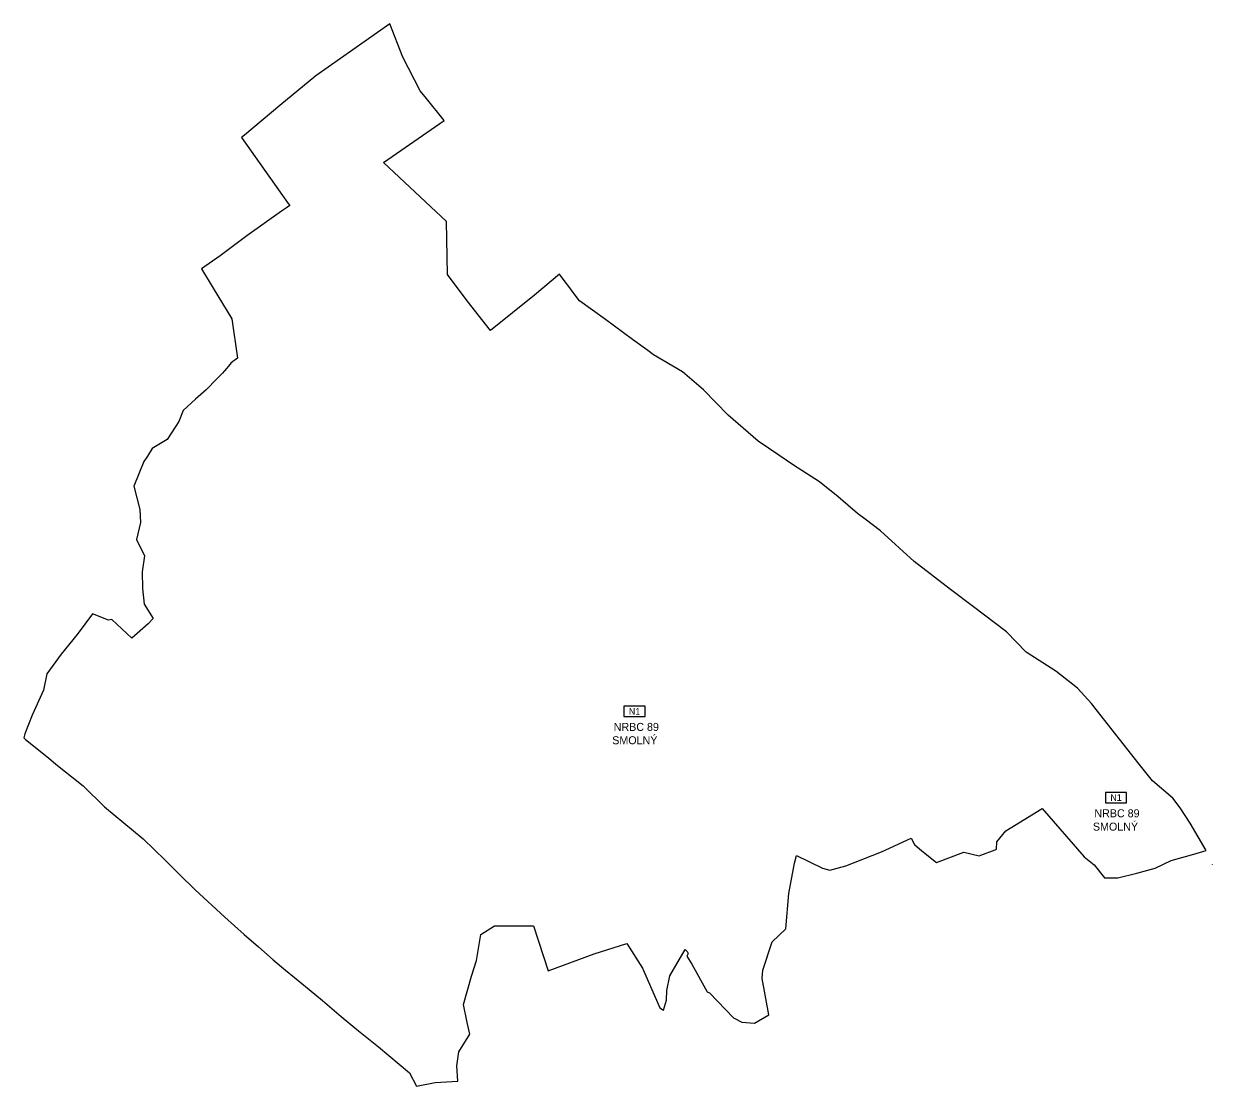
# Model space of a CAD drawing. Extents: x -546680 to -530218, y -1046521 to -1035695.
# Drawn here: x -543673 to -541891, y -1037288 to -1035695 of the extents above; entities that cross this region are included whole.
import ezdxf

# ---------------------------------------------------------------- set-up
doc = ezdxf.new("R2010")
doc.units = 0
for name, color, linetype in [('Vrstva 18', 7, 'Continuous'), ('Vrstva 3', 7, 'Continuous'), ('Vrstva 30', 7, 'Continuous'), ('Vrstva 82', 7, 'Continuous')]:
    doc.layers.add(name, color=color, linetype=linetype)

msp = doc.modelspace()

# ---------------------------------------------------------------- linework, layer by layer
at = {"layer": 'Vrstva 18'}
msp.add_line((-541891, -1036954.4), (-541890.8, -1036954.9), dxfattribs=at)
for points in [[(-541899.8, -1036934.3), (-541923.9, -1036893.3), (-541939.1, -1036869.9), (-541949.7, -1036855.6), (-541980.5, -1036829.7), (-542000.3, -1036804.7), (-542065.1, -1036722.5), (-542069.8, -1036716.4), (-542072.1, -1036713.8), (-542092.8, -1036690.7), (-542125.6, -1036665.3), (-542169.9, -1036636.7), (-542199.3, -1036606), (-542248.8, -1036568.9), (-542283.5, -1036542.7), (-542337.9, -1036500.9), (-542388.3, -1036455), (-542411.4, -1036437.3), (-542422.8, -1036428.7), (-542452, -1036403.6), (-542480, -1036381.3), (-542519, -1036356.5), (-542540.9, -1036341.6), (-542571.9, -1036320.4), (-542617, -1036281.3), (-542653.7, -1036243.4), (-542685.1, -1036216.3), (-542728.5, -1036190.8), (-542737.3, -1036184.4), (-542760.1, -1036167.7), (-542800.8, -1036138), (-542839.6, -1036109.9), (-542850.5, -1036095.4), (-542852.5, -1036092.7), (-542864, -1036077.3), (-542869.7, -1036069.8), (-542907.1, -1036101.7), (-542973.1, -1036154.5), (-543008.4, -1036110.2), (-543037.8, -1036070.6), (-543039.3, -1035990.9), (-543133.7, -1035902.3), (-543042.6, -1035839.4), (-543069.2, -1035806.4), (-543078.5, -1035794.9), (-543104.7, -1035744.6), (-543124.3, -1035694.5), (-543234.9, -1035772.4), (-543289.2, -1035817), (-543341.9, -1035861.5), (-543346.5, -1035865.2), (-543276.4, -1035963.9)], [(-543276.4, -1035963.9), (-543274.2, -1035967), (-543279.3, -1035970.3), (-543286.8, -1035975.7), (-543338.8, -1036012.6), (-543378.7, -1036042.3), (-543406.7, -1036061.9), (-543389.2, -1036090.9), (-543361.3, -1036136.8), (-543352.7, -1036195.7), (-543356.8, -1036199), (-543359.4, -1036201.1), (-543362.4, -1036203.4), (-543363.8, -1036205), (-543372.1, -1036214.7), (-543372.5, -1036215.2), (-543374.9, -1036218.2), (-543375.3, -1036218.6), (-543383.5, -1036226.9), (-543399.7, -1036243.4), (-543415.6, -1036257.2), (-543434.2, -1036274.3), (-543440.4, -1036290.8), (-543458.3, -1036318), (-543480.5, -1036331.6), (-543487.3, -1036342.7), (-543492.9, -1036350.6), (-543508.1, -1036387.7), (-543499, -1036422.7), (-543498.1, -1036442.3), (-543503.8, -1036468), (-543491.9, -1036492.5), (-543495.7, -1036516.1), (-543494.8, -1036541.3), (-543492.5, -1036564.8), (-543479.1, -1036586.3), (-543486.5, -1036594), (-543510.9, -1036615.5), (-543540.8, -1036587.9), (-543546.1, -1036588.7), (-543570, -1036579.1), (-543592.9, -1036610.1), (-543617, -1036639.6), (-543638.4, -1036669.3), (-543643.6, -1036693.8), (-543660.3, -1036731), (-543671.5, -1036759.2), (-543673.1, -1036765.1), (-543670.3, -1036767.8), (-543636.1, -1036795.4), (-543624.8, -1036804.5), (-543584.2, -1036837.2), (-543552, -1036868.5), (-543493.9, -1036916.7), (-543461.3, -1036948.8), (-543439.9, -1036969.6), (-543415.9, -1036993), (-543371.7, -1037034.1), (-543342.6, -1037060.1), (-543320.9, -1037078.7), (-543299.2, -1037098.1), (-543280.5, -1037113.3), (-543253.4, -1037135.7), (-543225.1, -1037158.9), (-543197.1, -1037182.9), (-543171, -1037204.6), (-543141.2, -1037228.7), (-543094.7, -1037267.6), (-543083.9, -1037287.5), (-543056, -1037281.9), (-543022.3, -1037279.9), (-543023.6, -1037256.8), (-543020.8, -1037236), (-543004, -1037209.4), (-543008.3, -1037191.8), (-543013.6, -1037165.2), (-543001.5, -1037122.4), (-542994, -1037099.2), (-542987.9, -1037060.2), (-542967.1, -1037047.1), (-542908.5, -1037047.1), (-542886.7, -1037114.3), (-542817.8, -1037088.9), (-542768.6, -1037073.7), (-542745.4, -1037110.5), (-542719.2, -1037169.9), (-542713.6, -1037173.4), (-542709.4, -1037158.5), (-542708.8, -1037144.2), (-542704.3, -1037122.2), (-542681, -1037082.7), (-542678.3, -1037085.7), (-542676.6, -1037088.4), (-542678.8, -1037092.5), (-542671.3, -1037104.6), (-542648.3, -1037146), (-542644.6, -1037147.4), (-542608.7, -1037184.9), (-542596.3, -1037191.7), (-542577.1, -1037192.8), (-542555.6, -1037180.4), (-542566, -1037125.8), (-542564.6, -1037113.6), (-542550.8, -1037070.8), (-542530.3, -1037051.6), (-542525.7, -1036998.8), (-542517.4, -1036953.1), (-542514.4, -1036941.4), (-542475.3, -1036960.4), (-542464.4, -1036963.6), (-542440.4, -1036956.9), (-542428.7, -1036952.4), (-542386.6, -1036936.3), (-542342.3, -1036915.6), (-542337.3, -1036925.1), (-542326.2, -1036934.7), (-542304.1, -1036952.2), (-542263.4, -1036936.6), (-542240.2, -1036942), (-542237.7, -1036941.1), (-542216.6, -1036933.1), (-542214.4, -1036932.3), (-542214.1, -1036921.3), (-542200.5, -1036904.7), (-542145.9, -1036870.9), (-542083, -1036943.6), (-542067.8, -1036955.8), (-542052.6, -1036975.3), (-542032.4, -1036974.9), (-542003.9, -1036968.3), (-541976.6, -1036960.8), (-541952.2, -1036949), (-541918.4, -1036939.5), (-541899.8, -1036934.3)]]:
    msp.add_lwpolyline(points, dxfattribs=at)
at = {"layer": 'Vrstva 30'}
for points in [[(-542773.1, -1036717.8), (-542773.1, -1036733.3), (-542741.4, -1036733.3), (-542741.4, -1036717.8), (-542773.1, -1036717.8)], [(-542051, -1036846.9), (-542051, -1036862.5), (-542019.3, -1036862.5), (-542019.3, -1036846.9), (-542051, -1036846.9)]]:
    msp.add_lwpolyline(points, dxfattribs=at)

# ---------------------------------------------------------------- texts
at = {"layer": 'Vrstva 3'}
for s, p in [('NRBC 89', (-542788.4, -1036754.8)), ('SMOLNÝ', (-542790.6, -1036774.8)), ('NRBC 89', (-542067.6, -1036884.3)), ('SMOLNÝ', (-542069.8, -1036904.3))]:
    msp.add_text(s, height=12, dxfattribs=at).set_placement(p)
at = {"layer": 'Vrstva 82'}
for p in [(-542765.7, -1036730.6), (-542043.6, -1036859.7)]:
    msp.add_text('N1', height=10, dxfattribs=at).set_placement(p)

doc.saveas('drawing.dxf')
